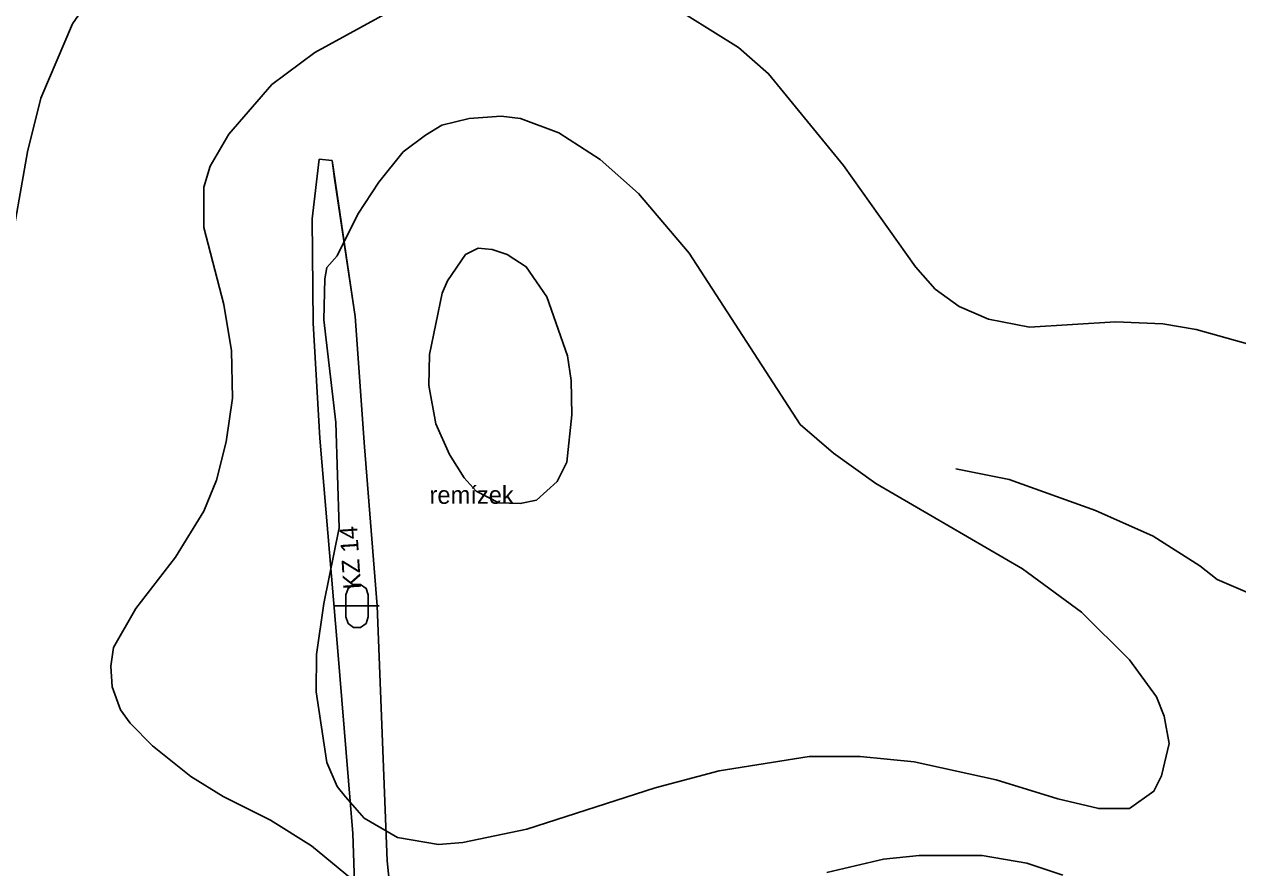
# Model space of a CAD drawing. Extents: x -645676 to -642474, y -1077513 to -1072613.
# Drawn here: x -644025.9 to -643751.8, y -1076900.3 to -1076709.8 of the extents above; entities that cross this region are included whole.
import ezdxf

# ---------------------------------------------------------------- set-up
doc = ezdxf.new("R2010")
doc.units = 0
for name, color, linetype in [('KRAJ_ZELEN_STAV', 7, 'Continuous'), ('Krajinn__zele____popis___stav', 7, 'Continuous'), ('KULTURY_STAV', 7, 'Continuous'), ('KULTURY_ZNACKY', 7, 'Continuous'), ('VRSTEVNICE', 7, 'Continuous')]:
    doc.layers.add(name, color=color, linetype=linetype)

# ---------------------------------------------------------------- blocks, each defined once
blk = doc.blocks.new('3$1600')
for points in [[(-0.5, 1.5), (-0.4, 1.79), (-0.15, 1.97), (0.16, 1.97), (0.41, 1.79), (0.51, 1.5), (0.51, 0.5), (0.41, 0.21), (0.16, 0.03), (-0.15, 0.03), (-0.4, 0.21), (-0.5, 0.5), (-0.5, 1.5)], [(-1, 1), (0.27, 1), (1, 1)]]:
    blk.add_lwpolyline(points)

msp = doc.modelspace()

# ---------------------------------------------------------------- linework, layer by layer
at = {"layer": 'KRAJ_ZELEN_STAV'}
msp.add_lwpolyline([(-643959.29, -1076740.26), (-643956.38, -1076740.61), (-643951.14, -1076775.84), (-643949.01, -1076805.23), (-643946.19, -1076841.17), (-643943.95, -1076898.75), (-643941.05, -1076926.71), (-643950.47, -1076928.12), (-643951.67, -1076892.59), (-643955.13, -1076850.47), (-643959.16, -1076803.32), (-643960.61, -1076777.3), (-643960.85, -1076753.76), (-643959.29, -1076740.26)], dxfattribs=at)
at = {"layer": 'KULTURY_STAV'}
for points in [[(-643959.29, -1076740.26), (-643956.38, -1076740.61), (-643955.78, -1076744.63), (-643951.14, -1076775.84), (-643949.01, -1076805.23), (-643946.19, -1076841.17), (-643943.95, -1076898.75), (-643941.05, -1076926.71), (-643945.07, -1076927.31), (-643950.47, -1076928.12), (-643951.67, -1076892.59), (-643955.13, -1076850.47), (-643959.16, -1076803.32), (-643960.61, -1076777.3), (-643960.85, -1076753.76), (-643959.29, -1076740.26)], [(-643959.29, -1076740.26), (-643960.85, -1076753.76), (-643960.61, -1076777.3), (-643959.16, -1076803.32), (-643955.13, -1076850.47), (-643951.67, -1076892.59), (-643950.47, -1076928.12), (-643945.07, -1076927.31), (-643941.05, -1076926.71), (-643943.95, -1076898.75), (-643946.19, -1076841.17), (-643949.01, -1076805.23), (-643951.14, -1076775.84), (-643955.78, -1076744.63), (-643956.38, -1076740.61), (-643959.29, -1076740.26)]]:
    msp.add_lwpolyline(points, dxfattribs=at)
at = {"layer": 'VRSTEVNICE'}
for points in [[(-644022.12, -1076726.49), (-644015.03, -1076709.69), (-644006.19, -1076696.94), (-643996.49, -1076687.53), (-643984.9, -1076680.43), (-643971.44, -1076674.93), (-643962.17, -1076672.03), (-643939, -1076667.54), (-643911.19, -1076664.65), (-643897.29, -1076662.48), (-643883.38, -1076658.86), (-643869.63, -1076653.64), (-643857.61, -1076645.82), (-643844.86, -1076634.24)], [(-643945.95, -1076907.8), (-643961.01, -1076895.35), (-643970.28, -1076889.56), (-643980.99, -1076884.2), (-643988.24, -1076879.71), (-643996.92, -1076872.76), (-644001.99, -1076867.69), (-644004.17, -1076864.65), (-644006.05, -1076859.43), (-644006.34, -1076854.8), (-644005.76, -1076850.6), (-644000.69, -1076841.76), (-643991.71, -1076830.18), (-643985.34, -1076819.75), (-643982.44, -1076812.8), (-643980.27, -1076804.11), (-643978.82, -1076794.26), (-643979.11, -1076783.55), (-643980.85, -1076773.12), (-643985.34, -1076755.74), (-643985.34, -1076746.62), (-643983.89, -1076741.84), (-643979.69, -1076734.6), (-643969.99, -1076723.45), (-643960.28, -1076716.21), (-643942.76, -1076706.65)], [(-643876.14, -1076707.8), (-643864.56, -1076715.05)], [(-643864.56, -1076715.05), (-643857.75, -1076720.98), (-643840.81, -1076741.69), (-643824.59, -1076764.58), (-643820.1, -1076769.64), (-643814.74, -1076773.55), (-643808.08, -1076776.45), (-643798.81, -1076778.19), (-643779.4, -1076777.03), (-643768.69, -1076777.46)], [(-644028.06, -1076754.87), (-644025.16, -1076738.65), (-644022.12, -1076726.49)], [(-643768.69, -1076777.46), (-643761.16, -1076778.77), (-643742.04, -1076784.13)], [(-643632.98, -1076800.83), (-643640.66, -1076801.23), (-643646.46, -1076802.37), (-643655.73, -1076805.41), (-643667.31, -1076811.93), (-643678.32, -1076820.19), (-643692.8, -1076833.08), (-643702.94, -1076840.75), (-643708.73, -1076843.5), (-643712.65, -1076844.8), (-643717.42, -1076845.24), (-643723.21, -1076844.95), (-643740.45, -1076842.05), (-643756.4, -1076835.24), (-643760.36, -1076832.11), (-643770.86, -1076825.4), (-643783.89, -1076819.61), (-643803.44, -1076812.66), (-643815.46, -1076810.19)], [(-643791.28, -1076902.01), (-643799.39, -1076899.26), (-643809.53, -1076897.52), (-643823.72, -1076897.52), (-643831.83, -1076898.39), (-643844.6, -1076901.41)]]:
    msp.add_lwpolyline(points, dxfattribs=at)
for points in [[(-643843.12, -1076806.72), (-643850.65, -1076800.2), (-643875.71, -1076761.53), (-643887.15, -1076748.07), (-643895.84, -1076740.39), (-643905.11, -1076734.31), (-643913.8, -1076731.12), (-643918.14, -1076730.54), (-643925.38, -1076731.12), (-643931.6, -1076732.62), (-643935.23, -1076734.89), (-643940.3, -1076738.65), (-643945.8, -1076745.46), (-643950.58, -1076752.7), (-643955.22, -1076762.11), (-643957.53, -1076764.72), (-643957.97, -1076767.33), (-643958.26, -1076776.6), (-643955.51, -1076799.77), (-643954.78, -1076823.52), (-643958.26, -1076840.61), (-643959.85, -1076852.19), (-643959.99, -1076860.59), (-643957.53, -1076876.52), (-643955.2, -1076881.94), (-643953.33, -1076884.34), (-643949.13, -1076889.12), (-643941.6, -1076893.47), (-643932.33, -1076895.06), (-643926.83, -1076894.62), (-643912.35, -1076891.58), (-643883.38, -1076882.31), (-643868.9, -1076878.4), (-643848.63, -1076875.22), (-643837.04, -1076875.22), (-643824.88, -1076876.38), (-643806.34, -1076880.43), (-643792.44, -1076884.78), (-643783.17, -1076886.95), (-643776.22, -1076886.95), (-643770.71, -1076883.04), (-643768.98, -1076879.56), (-643767.26, -1076872.29), (-643768.4, -1076866.1), (-643770.13, -1076861.75), (-643776.22, -1076853.35), (-643787.08, -1076842.63), (-643800.4, -1076832.79), (-643833.57, -1076813.52)], [(-643907.86, -1076771.38), (-643912.49, -1076764.58), (-643916.84, -1076761.82), (-643920.17, -1076760.67), (-643923.38, -1076760.36), (-643926.19, -1076761.85), (-643930.31, -1076767.76), (-643931.47, -1076770.51), (-643934.36, -1076784.42), (-643934.51, -1076791.37), (-643932.91, -1076800.06), (-643929.87, -1076807.01), (-643926.54, -1076812.22), (-643923.79, -1076815.26), (-643918.72, -1076817.87), (-643913.89, -1076818.03), (-643910.18, -1076817.29), (-643905.54, -1076813.09), (-643903.37, -1076808.75), (-643902.21, -1076798.03), (-643902.37, -1076790.27), (-643903.22, -1076784.71)]]:
    msp.add_lwpolyline(points, close=True, dxfattribs=at)

# ---------------------------------------------------------------- block references
at = {"layer": 'KULTURY_ZNACKY', "xscale": 5, "yscale": 5}
msp.add_blockref('3$1600', (-643950.75, -1076846.18), dxfattribs=at)

# ---------------------------------------------------------------- texts
at = {"layer": 'Krajinn__zele____popis___stav'}
msp.add_text('remízek', height=4, dxfattribs=at).set_placement((-643934.35, -1076818.12))
msp.add_text('KZ 14', height=4, rotation=93.621, dxfattribs=at).set_placement((-643949.81, -1076837.29))

doc.saveas('drawing.dxf')
